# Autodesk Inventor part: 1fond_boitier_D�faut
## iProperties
Created: 2011-01
Part Number: 1fond_boitier_D�faut
Document SubType Name: Modeling
Designer: eric
Density: 1 g/cm^3
Mass: 13.8423 g
Surface Area: 149.303 cm^2
Volume: 13.8423 cm^3
Author: eric
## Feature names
1. Base1
